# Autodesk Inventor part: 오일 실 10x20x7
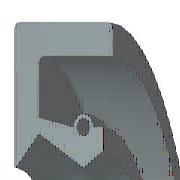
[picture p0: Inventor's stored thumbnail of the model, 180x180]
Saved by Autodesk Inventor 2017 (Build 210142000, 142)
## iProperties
IsCustomPart: 1
Created: 2012-02
Part Number: 오일 실 10x20x7
Material: 고무
Description: 오일-실
Document SubType Name: Modeling
Standard: KS B 2804
Designer: mduedu
Standards Organization: KS
Language: ko-KR
Size Designation: D - 10 20 7
Categories: <MemberInstance><Categories><Category DisplayName="샤프트 부품" InternalName="7f7aeb1f-a693-4053-b835-cee3144e0d98" Mnemonic="SHFT"><Category DisplayName="실링" Intern
Density: 0.93 g/cm^3
Appearance: 고무 - 검은색 - 버전 1.1
Author: mduedu
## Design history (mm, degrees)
revolve "본체" stored, may be unused: angle "d17" = 90 deg
revolve "스프링1" stored, may be unused: angle "d18" = 90 deg
body "Solid1"
sketch "스케치1"
  geometry: L1 (0, 10)-(7, 10); L2 (7, 8.25)-(1.75, 8.25); L3 (1.75, 6.75)-(4.9, 5); L4 (4.9, 5)-(0, 5); L5 (0, 0)-(9.586, 0) reference; L6 (4.9, 5)-(6.3, 5.875); L7 (0, 18)-(0, -3) reference; L8 (-1.941, 0)-(11.507, 0) reference; L9 (4.2, 7.1)-(1.75, 7.59); L10 (1.75, 7.59)-(1.75, 8.25); L11 (0, 10)-(0, 5.088); L12 (4.9, 5)-(0, 5); L13 (1.75, 6.75)-(0.152, 5.028); L14 (7, 10)-(7, 8.25); L15 (5.6, 7.1)-(6.3, 7.1); L16 (6.3, 7.1)-(6.3, 5.875); C1 r 0.455 at (4.9, 7.1); A1 r 0.7 centre (4.9, 7.1) between (5.6, 7.1) and (4.2, 7.1); A2 r 0.088 centre (0.088, 5.088) between (0, 5.088) and (0.152, 5.028); 1 further point
  constraints: 28 end point, 5 horizontal alignment, 5 point on line, 4 point on circle, 4 vertical alignment, 3 centre point, 3 tangent, 2 collinear, 2 horizontal, 2 perpendicular, 1 coincident, 1 parallel
  dimensions: "d0" = 20 diameter of L1 L5 (= SD2); "d1" = 1.75 distance of L1.end L2.start (= SD); "d2" = 0.91 diameter of C1 (= SPDI); "d3" = 1.4 diameter of A1 (= SPDA); "d4" = 10 diameter of L3.end L5 (= NND); "d5" = 13.5 diameter of L3.start L5 (= TKDM); "d7" = 15.18 diameter of L9.end L5 (= TKDM + 0.24 x SWDT); "d8" = 1.75 distance between parallel lines of L11 L10 (= SD); "d9" = 4.9 distance from line of L11 C1.centre (= SPDST); "d10" = 14.2 diameter of C1.centre L5 (= HLDM); "d11" = 0.0875 radius of A2 (= 0.25 x LAB); "d12" = 6.3 distance between parallel lines of L11 L16 (= SDI); "d13" = 11.75 diameter of L6.end L5 (= ABDM); "d14" = 7 distance from line of L11 L1.end (= SWDT)
fillet "모깎기1" dims "d6" = 0.3 (= RR)
other parameters: "SD2" = 20 [user parameter; used in 1 equation term], "SWDT" = 7 [user parameter; used in 2 equation terms], "RR" = 0.3 [user parameter; used in 1 equation term], "SD" = 1.75 [user parameter; used in 2 equation terms], "NND" = 10 [user parameter; used in 1 equation term], "SPDA" = 1.4 [user parameter; used in 1 equation term], "SPDI" = 0.91 [user parameter; used in 1 equation term], "TKDM" = 13.5 [user parameter; used in 2 equation terms], "HLDM" = 14.2 [user parameter; used in 1 equation term], "ABDM" = 11.75 [user parameter; used in 1 equation term], "SDI" = 6.3 [user parameter; used in 1 equation term], "SPDST" = 4.9 [user parameter; used in 1 equation term], "LAB" = 0.35 [user parameter; used in 1 equation term], "d15" = 0, "d16" = 0, "d19" = 0
